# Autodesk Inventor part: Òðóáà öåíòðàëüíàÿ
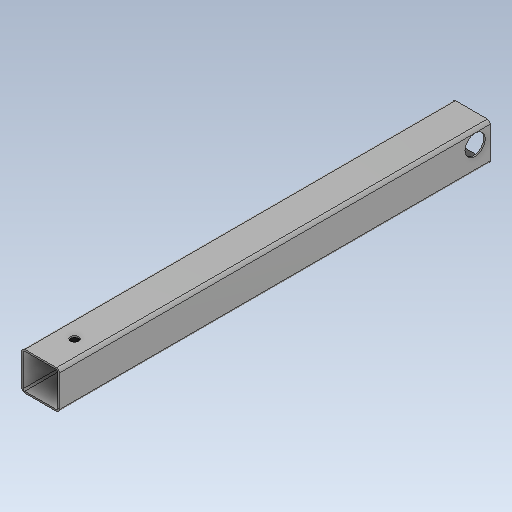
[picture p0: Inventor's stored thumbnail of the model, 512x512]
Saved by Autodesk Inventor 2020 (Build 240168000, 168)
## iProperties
Created: 1900-01
Part Number: Òðóáà öåíòðàëüíàÿ
Material: Générique
Document SubType Name: Modeling
Designer: bruno
Density: 1 g/cm^3
Appearance: Par défaut
Author: bruno
Revision Number: ANYUNSPECIFIED
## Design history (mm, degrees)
feature "Base1"
node "Solide1"
